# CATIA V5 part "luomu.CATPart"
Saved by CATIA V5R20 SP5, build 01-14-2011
Part number: 螺母
Bounding box of the stored display mesh (mm): x -30 to 30, y -26.006 to 26.006, z -10 to 10
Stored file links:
  E:\画图\luomu.CATPart
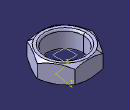
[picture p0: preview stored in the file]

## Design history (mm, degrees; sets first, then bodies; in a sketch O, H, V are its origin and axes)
Body1 (main body)
  Sketch1 on xy-plane, origin (0, 0, 0), H (1, 0, 0), V (0, 1, 0)
    point P1 (14.9558, -26.0063)
    point P2 (30, -0.0511)
    point P3 (15.0442, 25.9552)
    point P4 (-14.9558, 26.0063)
    point P5 (-30, 0.0511)
    point P6 (-15.0442, -25.9552)
    point P7 (22.4779, -13.0287)
    line L1 (14.9558, -26.0063) -> (30, -0.0511)
    line L2 (30, -0.0511) -> (15.0442, 25.9552)
    line L3 (15.0442, 25.9552) -> (-14.9558, 26.0063)
    line L4 (-14.9558, 26.0063) -> (-30, 0.0511)
    line L5 (-30, 0.0511) -> (-15.0442, -25.9552)
    line L6 (-15.0442, -25.9552) -> (14.9558, -26.0063)
    construction line L7 (0, 0) -> (22.4779, -13.0287)
    construction circle A1 centre (0, 0) radius 30
    construction arc A2 centre (-30, 0.0511) radius 30 from (-14.9558, 26.0063) to (-15.0442, -25.9552) cw
    construction arc A3 centre (30, -0.0511) radius 30 from (15.0442, 25.9552) to (14.9558, -26.0063) ccw
    circle A4 centre (0, 0) radius 20
    distance P5 P2 = 60
    radius A4 = 20
    coincidence: A1 P1, A1 P2, A1 P3, A1 P4, A1 P5, A1 P6, A2 O, A3 O
    midpoint: P7 L1
    parallelism: L1 L4
  Pad1: profile Sketch1, direction (0, 0, 1), length 10, mirrored extent
  Sketch2 on face of Pad1 from Sketch1.L2, origin (22.5221, 12.9521, 0), H (-0.3927, 0.6829, -0.616), V (-0.3071, 0.534, 0.7878)
  Sketch3 on yz-plane, origin (0, 0, 0), H (0, 1, 0), V (0, 0, 1)
    point P1 (25, 10)
    line L1 (25, 10) -> (48.6517, 10)
    line L2 (48.6517, 10) -> (48.6517, -3.6553)
    line L3 (48.6517, -3.6553) -> (25, 10)
    reference projected line E1 (-0.0511, 10) -> (25.9552, 10) from edge [face of Pad1 from Sketch1.L2 | end face of Pad1]
    angle L1 L3 = 30
    distance V P1 = 25
    horizontal: L1 H
    vertical: L2 V
    coincidence: L1 E1
  Groove1: profile Sketch3, axis axis of face of Pad1 from Sketch1.A4, angle 360
  Mirror1: of Groove1, about xy-plane
  Fillet1: radius 2, on edge [face of Pad1 from Sketch1.A4 | start face of Pad1]; edge [end face of Pad1 | face of Pad1 from Sketch1.A4]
